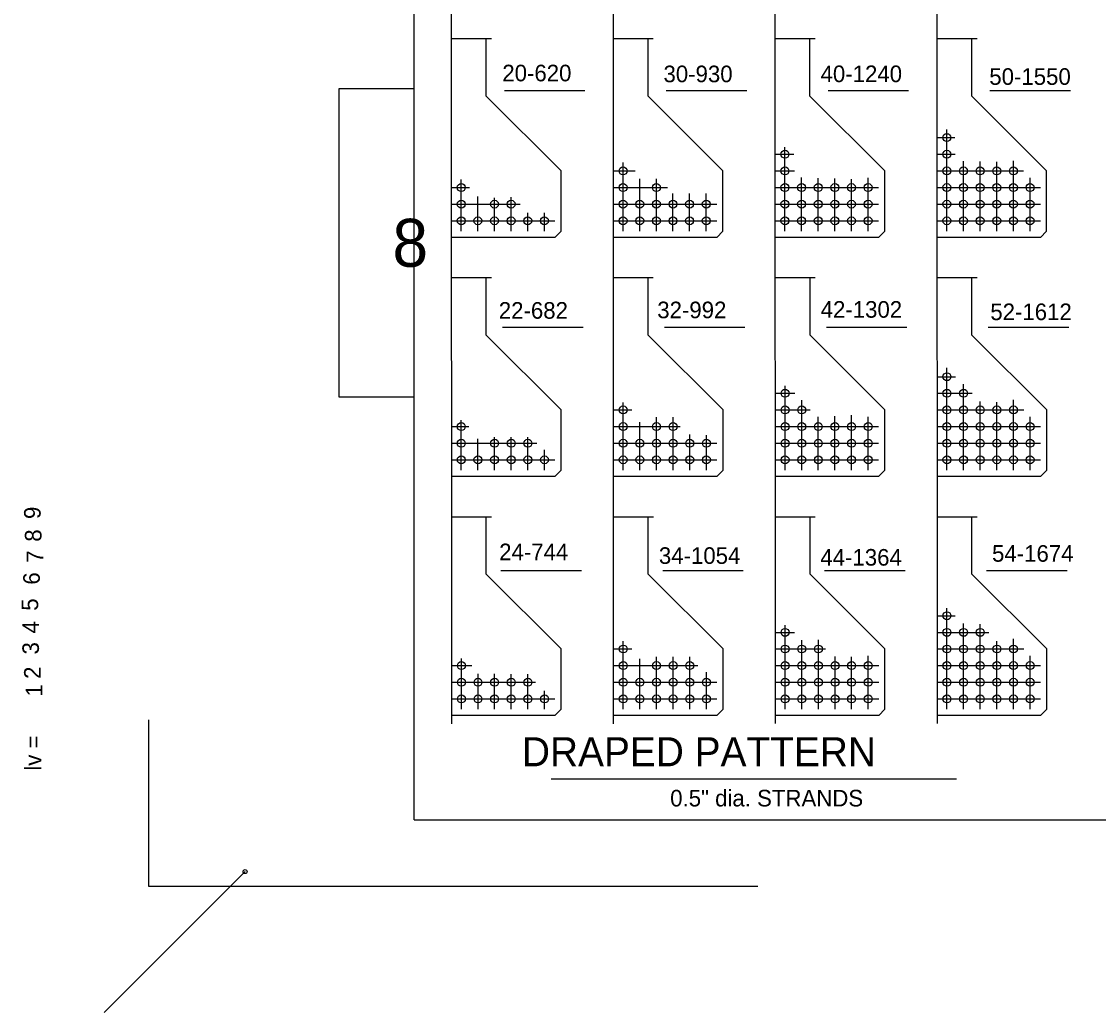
# Model space of a CAD drawing. Extents: x 1005 to 1123, y 2008 to 2074.
# Drawn here: x 1006.11 to 1027.73, y 2009.17 to 2029.07 of the extents above; entities that cross this region are included whole.
import ezdxf

# ---------------------------------------------------------------- set-up
doc = ezdxf.new("R2010")
doc.units = 0
for name, color, linetype in [('Level 1', 7, 'Continuous'), ('Level 2', 7, 'Continuous'), ('Level 3', 7, 'Continuous'), ('Level 4', 7, 'Continuous'), ('Level 49', 7, 'Continuous'), ('Level 5', 7, 'Continuous'), ('Level 6', 7, 'Continuous'), ('Level 7', 7, 'Continuous'), ('Level 8', 7, 'Continuous'), ('Level 9', 7, 'Continuous')]:
    doc.layers.add(name, color=color, linetype=linetype)

msp = doc.modelspace()

# ---------------------------------------------------------------- linework, layer by layer
at = {"layer": 'Level 1'}
for p, q in [((1013.989, 2013.041), (1013.989, 2069.04)), ((1008.656, 2015.048), (1008.656, 2011.708)), ((1013.989, 2013.041), (1097.657, 2013.041)), ((1008.656, 2011.708), (1020.89, 2011.708))]:
    msp.add_line(p, q, dxfattribs=at)
msp.add_lwpolyline([(1013.989, 2027.72), (1012.476, 2027.72), (1012.476, 2021.53), (1013.989, 2021.53)], close=True, dxfattribs=at)
at = {"layer": 'Level 2'}
for p, q in [((1016.744, 2013.865), (1024.877, 2013.865)), ((1007.769, 2009.17), (1010.598, 2011.999))]:
    msp.add_line(p, q, dxfattribs=at)
at = {"layer": 'Level 49'}
msp.add_circle((1010.597, 2011.999), 0.0405, dxfattribs=at)
at = {"layer": 'Level 8'}
for p, q in [((1014.732, 2038.643), (1014.739, 2014.968)), ((1017.982, 2038.644), (1017.989, 2014.969)), ((1021.232, 2038.645), (1021.239, 2014.97)), ((1024.482, 2038.646), (1024.489, 2014.971)), ((1014.734, 2028.726), (1015.542, 2028.726)), ((1014.769, 2028.726), (1015.542, 2028.726)), ((1015.437, 2027.572), (1015.437, 2028.726)), ((1017.984, 2028.726), (1018.792, 2028.726)), ((1018.019, 2028.726), (1018.792, 2028.726)), ((1018.687, 2027.572), (1018.687, 2028.726)), ((1021.234, 2028.726), (1022.042, 2028.726)), ((1021.269, 2028.726), (1022.042, 2028.726)), ((1021.937, 2027.572), (1021.937, 2028.726)), ((1024.484, 2028.726), (1025.292, 2028.726)), ((1024.519, 2028.726), (1025.292, 2028.726)), ((1025.187, 2027.572), (1025.187, 2028.726)), ((1016.94, 2026.069), (1015.437, 2027.572)), ((1015.802, 2027.681), (1017.418, 2027.681)), ((1020.19, 2026.069), (1018.687, 2027.572)), ((1019.052, 2027.681), (1020.668, 2027.681)), ((1023.44, 2026.069), (1021.937, 2027.572)), ((1022.302, 2027.681), (1023.918, 2027.681)), ((1026.69, 2026.069), (1025.187, 2027.572)), ((1025.552, 2027.681), (1027.168, 2027.681)), ((1024.686, 2024.858), (1024.686, 2026.898)), ((1024.485, 2026.737), (1024.846, 2026.737)), ((1021.436, 2024.858), (1021.436, 2026.549)), ((1018.186, 2024.858), (1018.186, 2026.237)), ((1021.235, 2026.403), (1021.616, 2026.403)), ((1024.485, 2026.403), (1024.856, 2026.403)), ((1025.02, 2024.858), (1025.02, 2026.268)), ((1025.354, 2024.858), (1025.354, 2026.258)), ((1025.688, 2024.858), (1025.688, 2026.248)), ((1026.022, 2024.858), (1026.022, 2026.271)), ((1016.94, 2024.858), (1016.94, 2026.069)), ((1017.986, 2026.069), (1018.429, 2026.069)), ((1020.19, 2024.858), (1020.19, 2026.069)), ((1021.235, 2026.069), (1021.626, 2026.069)), ((1023.44, 2024.858), (1023.44, 2026.069)), ((1024.485, 2026.069), (1026.228, 2026.069)), ((1026.69, 2024.858), (1026.69, 2026.069)), ((1014.936, 2024.858), (1014.936, 2025.898)), ((1018.52, 2024.858), (1018.52, 2025.909)), ((1018.854, 2024.858), (1018.854, 2025.909)), ((1021.77, 2024.858), (1021.77, 2025.938)), ((1022.104, 2024.858), (1022.104, 2025.926)), ((1022.438, 2024.858), (1022.438, 2025.915)), ((1022.772, 2024.858), (1022.772, 2025.903)), ((1023.106, 2024.858), (1023.106, 2025.933)), ((1026.356, 2024.858), (1026.356, 2025.933)), ((1014.735, 2025.735), (1015.1, 2025.735)), ((1017.985, 2025.735), (1019.079, 2025.735)), ((1019.188, 2024.858), (1019.188, 2025.617)), ((1019.522, 2024.858), (1019.522, 2025.617)), ((1019.856, 2024.858), (1019.856, 2025.617)), ((1021.235, 2025.735), (1023.315, 2025.735)), ((1024.485, 2025.735), (1026.565, 2025.735)), ((1014.736, 2025.401), (1016.122, 2025.401)), ((1015.27, 2024.858), (1015.27, 2025.557)), ((1015.604, 2024.858), (1015.604, 2025.529)), ((1015.938, 2024.858), (1015.938, 2025.541)), ((1017.985, 2025.401), (1020.065, 2025.401)), ((1021.235, 2025.401), (1023.315, 2025.401)), ((1024.485, 2025.401), (1026.565, 2025.401)), ((1016.272, 2024.858), (1016.272, 2025.23)), ((1016.606, 2024.858), (1016.606, 2025.23)), ((1014.736, 2025.067), (1016.815, 2025.067)), ((1017.986, 2025.067), (1020.065, 2025.067)), ((1021.236, 2025.067), (1023.315, 2025.067)), ((1024.486, 2025.067), (1026.565, 2025.067)), ((1016.815, 2024.733), (1014.736, 2024.733)), ((1016.815, 2024.733), (1016.94, 2024.858)), ((1020.065, 2024.733), (1017.986, 2024.733)), ((1020.065, 2024.733), (1020.19, 2024.858)), ((1023.315, 2024.733), (1021.236, 2024.733)), ((1023.315, 2024.733), (1023.44, 2024.858)), ((1026.565, 2024.733), (1024.486, 2024.733)), ((1026.565, 2024.733), (1026.69, 2024.858)), ((1014.735, 2023.926), (1015.543, 2023.926)), ((1014.771, 2023.926), (1015.543, 2023.926)), ((1015.439, 2022.772), (1015.439, 2023.926)), ((1017.985, 2023.926), (1018.793, 2023.926)), ((1018.021, 2023.926), (1018.793, 2023.926)), ((1018.689, 2022.772), (1018.689, 2023.926)), ((1021.235, 2023.926), (1022.043, 2023.926)), ((1021.271, 2023.926), (1022.043, 2023.926)), ((1021.939, 2022.772), (1021.939, 2023.926)), ((1024.485, 2023.926), (1025.293, 2023.926)), ((1024.521, 2023.926), (1025.293, 2023.926)), ((1025.189, 2022.772), (1025.189, 2023.926)), ((1016.942, 2021.269), (1015.439, 2022.772)), ((1015.768, 2022.932), (1017.383, 2022.932)), ((1020.192, 2021.269), (1018.689, 2022.772)), ((1019.018, 2022.932), (1020.633, 2022.932)), ((1023.442, 2021.269), (1021.939, 2022.772)), ((1022.268, 2022.932), (1023.883, 2022.932)), ((1026.692, 2021.269), (1025.189, 2022.772)), ((1025.518, 2022.932), (1027.133, 2022.932)), ((1024.688, 2020.058), (1024.688, 2022.116)), ((1024.486, 2021.937), (1024.863, 2021.937)), ((1021.438, 2020.058), (1021.438, 2021.755)), ((1025.022, 2020.058), (1025.022, 2021.787)), ((1021.236, 2021.603), (1021.631, 2021.603)), ((1021.772, 2020.058), (1021.772, 2021.463)), ((1024.486, 2021.603), (1025.193, 2021.603)), ((1026.024, 2020.058), (1026.024, 2021.471)), ((1016.942, 2020.058), (1016.942, 2021.269)), ((1017.987, 2021.269), (1018.362, 2021.269)), ((1018.188, 2020.058), (1018.188, 2021.416)), ((1020.192, 2020.058), (1020.192, 2021.269)), ((1021.237, 2021.269), (1021.939, 2021.269)), ((1023.442, 2020.058), (1023.442, 2021.269)), ((1024.487, 2021.269), (1026.229, 2021.269)), ((1025.356, 2020.058), (1025.356, 2021.436)), ((1025.69, 2020.058), (1025.69, 2021.426)), ((1026.692, 2020.058), (1026.692, 2021.269)), ((1014.938, 2020.058), (1014.938, 2021.066)), ((1018.522, 2020.058), (1018.522, 2021.021)), ((1018.856, 2020.058), (1018.856, 2021.121)), ((1019.19, 2020.058), (1019.19, 2021.121)), ((1022.106, 2020.058), (1022.106, 2021.129)), ((1022.44, 2020.058), (1022.44, 2021.147)), ((1022.774, 2020.058), (1022.774, 2021.164)), ((1023.108, 2020.058), (1023.108, 2021.133)), ((1026.358, 2020.058), (1026.358, 2021.133)), ((1014.737, 2020.935), (1015.09, 2020.935)), ((1017.987, 2020.935), (1019.333, 2020.935)), ((1021.237, 2020.935), (1023.317, 2020.935)), ((1024.487, 2020.935), (1026.567, 2020.935)), ((1014.737, 2020.601), (1016.456, 2020.601)), ((1015.272, 2020.058), (1015.272, 2020.687)), ((1015.606, 2020.058), (1015.606, 2020.723)), ((1015.94, 2020.058), (1015.94, 2020.723)), ((1016.274, 2020.058), (1016.274, 2020.723)), ((1017.987, 2020.601), (1020.067, 2020.601)), ((1019.524, 2020.058), (1019.524, 2020.775)), ((1019.858, 2020.058), (1019.858, 2020.766)), ((1021.237, 2020.601), (1023.317, 2020.601)), ((1024.487, 2020.601), (1026.567, 2020.601)), ((1016.608, 2020.058), (1016.608, 2020.468)), ((1014.737, 2020.267), (1016.817, 2020.267)), ((1017.987, 2020.267), (1020.067, 2020.267)), ((1021.237, 2020.267), (1023.317, 2020.267)), ((1024.487, 2020.267), (1026.567, 2020.267)), ((1016.817, 2019.933), (1016.942, 2020.058)), ((1020.067, 2019.933), (1020.192, 2020.058)), ((1023.317, 2019.933), (1023.442, 2020.058)), ((1026.567, 2019.933), (1026.692, 2020.058)), ((1016.817, 2019.933), (1014.737, 2019.933)), ((1020.067, 2019.933), (1017.987, 2019.933)), ((1023.317, 2019.933), (1021.237, 2019.933)), ((1026.567, 2019.933), (1024.487, 2019.933)), ((1014.737, 2019.126), (1015.545, 2019.126)), ((1014.772, 2019.126), (1015.545, 2019.126)), ((1015.44, 2017.972), (1015.44, 2019.126)), ((1017.987, 2019.126), (1018.795, 2019.126)), ((1018.022, 2019.126), (1018.795, 2019.126)), ((1018.69, 2017.972), (1018.69, 2019.126)), ((1021.237, 2019.126), (1022.045, 2019.126)), ((1021.272, 2019.126), (1022.045, 2019.126)), ((1021.94, 2017.972), (1021.94, 2019.126)), ((1024.487, 2019.126), (1025.295, 2019.126)), ((1024.522, 2019.126), (1025.295, 2019.126)), ((1025.19, 2017.972), (1025.19, 2019.126)), ((1015.733, 2018.046), (1017.349, 2018.046)), ((1018.983, 2018.046), (1020.599, 2018.046)), ((1022.233, 2018.046), (1023.849, 2018.046)), ((1025.483, 2018.046), (1027.099, 2018.046)), ((1016.943, 2016.469), (1015.44, 2017.972)), ((1020.193, 2016.469), (1018.69, 2017.972)), ((1023.443, 2016.469), (1021.94, 2017.972)), ((1026.693, 2016.469), (1025.19, 2017.972)), ((1024.488, 2017.137), (1024.851, 2017.137)), ((1024.689, 2015.258), (1024.689, 2017.289)), ((1021.439, 2015.258), (1021.439, 2016.949)), ((1025.023, 2015.258), (1025.023, 2016.984)), ((1025.357, 2015.258), (1025.357, 2016.97)), ((1021.238, 2016.803), (1021.626, 2016.803)), ((1024.488, 2016.803), (1025.53, 2016.803)), ((1018.189, 2015.258), (1018.189, 2016.623)), ((1021.773, 2015.258), (1021.773, 2016.644)), ((1022.107, 2015.258), (1022.107, 2016.65)), ((1025.691, 2015.258), (1025.691, 2016.625)), ((1026.025, 2015.258), (1026.025, 2016.671)), ((1014.939, 2015.258), (1014.939, 2016.276)), ((1016.943, 2015.258), (1016.943, 2016.469)), ((1017.988, 2016.469), (1018.36, 2016.469)), ((1018.523, 2015.258), (1018.523, 2016.272)), ((1018.857, 2015.258), (1018.857, 2016.309)), ((1019.191, 2015.258), (1019.191, 2016.309)), ((1019.525, 2015.258), (1019.525, 2016.309)), ((1020.193, 2015.258), (1020.193, 2016.469)), ((1021.238, 2016.469), (1022.248, 2016.469)), ((1022.441, 2015.258), (1022.441, 2016.316)), ((1022.775, 2015.258), (1022.775, 2016.312)), ((1023.109, 2015.258), (1023.109, 2016.333)), ((1023.443, 2015.258), (1023.443, 2016.469)), ((1024.488, 2016.469), (1026.231, 2016.469)), ((1026.359, 2015.258), (1026.359, 2016.333)), ((1026.693, 2015.258), (1026.693, 2016.469)), ((1014.738, 2016.135), (1015.148, 2016.135)), ((1017.988, 2016.135), (1019.689, 2016.135)), ((1021.238, 2016.135), (1023.318, 2016.135)), ((1024.488, 2016.135), (1026.568, 2016.135)), ((1015.273, 2015.258), (1015.273, 2015.971)), ((1015.607, 2015.258), (1015.607, 2015.968)), ((1015.941, 2015.258), (1015.941, 2015.965)), ((1016.275, 2015.258), (1016.275, 2015.961)), ((1019.859, 2015.258), (1019.859, 2016.005)), ((1014.738, 2015.801), (1016.428, 2015.801)), ((1016.609, 2015.258), (1016.609, 2015.629)), ((1017.988, 2015.801), (1020.068, 2015.801)), ((1021.238, 2015.801), (1023.318, 2015.801)), ((1024.488, 2015.801), (1026.568, 2015.801)), ((1014.738, 2015.467), (1016.818, 2015.467)), ((1017.988, 2015.467), (1020.068, 2015.467)), ((1021.238, 2015.467), (1023.318, 2015.467)), ((1024.488, 2015.467), (1026.568, 2015.467)), ((1016.818, 2015.133), (1016.943, 2015.258)), ((1020.068, 2015.133), (1020.193, 2015.258)), ((1023.318, 2015.133), (1023.443, 2015.258)), ((1026.568, 2015.133), (1026.693, 2015.258)), ((1016.818, 2015.133), (1014.739, 2015.133)), ((1020.068, 2015.133), (1017.989, 2015.133)), ((1023.318, 2015.133), (1021.239, 2015.133)), ((1026.568, 2015.133), (1024.489, 2015.133))]:
    msp.add_line(p, q, dxfattribs=at)
for centre in [(1024.686, 2026.737), (1021.436, 2026.403), (1024.686, 2026.403), (1018.186, 2026.069), (1021.436, 2026.069), (1024.686, 2026.069), (1025.02, 2026.069), (1025.354, 2026.069), (1025.688, 2026.069), (1026.022, 2026.069), (1014.936, 2025.735), (1018.186, 2025.735), (1018.854, 2025.735), (1021.436, 2025.735), (1021.77, 2025.735), (1022.104, 2025.735), (1022.438, 2025.735), (1022.772, 2025.735), (1023.106, 2025.735), (1024.686, 2025.735), (1025.02, 2025.735), (1025.354, 2025.735), (1025.688, 2025.735), (1026.022, 2025.735), (1026.356, 2025.735), (1014.936, 2025.401), (1015.604, 2025.401), (1015.938, 2025.401), (1018.186, 2025.401), (1018.52, 2025.401), (1018.854, 2025.401), (1019.188, 2025.401), (1019.522, 2025.401), (1019.856, 2025.401), (1021.436, 2025.401), (1021.77, 2025.401), (1022.104, 2025.401), (1022.438, 2025.401), (1022.772, 2025.401), (1023.106, 2025.401), (1024.686, 2025.401), (1025.02, 2025.401), (1025.354, 2025.401), (1025.688, 2025.401), (1026.022, 2025.401), (1026.356, 2025.401), (1014.936, 2025.067), (1015.27, 2025.067), (1015.604, 2025.067), (1015.938, 2025.067), (1016.272, 2025.067), (1016.606, 2025.067), (1018.186, 2025.067), (1018.52, 2025.067), (1018.854, 2025.067), (1019.188, 2025.067), (1019.522, 2025.067), (1019.856, 2025.067), (1021.436, 2025.067), (1021.77, 2025.067), (1022.104, 2025.067), (1022.438, 2025.067), (1022.772, 2025.067), (1023.106, 2025.067), (1024.686, 2025.067), (1025.02, 2025.067), (1025.354, 2025.067), (1025.688, 2025.067), (1026.022, 2025.067), (1026.356, 2025.067), (1024.688, 2021.937), (1021.438, 2021.603), (1024.688, 2021.603), (1025.022, 2021.603), (1018.188, 2021.269), (1021.438, 2021.269), (1021.772, 2021.269), (1024.688, 2021.269), (1025.022, 2021.269), (1025.356, 2021.269), (1025.69, 2021.269), (1026.024, 2021.269), (1014.938, 2020.935), (1018.188, 2020.935), (1018.856, 2020.935), (1019.19, 2020.935), (1021.438, 2020.935), (1021.772, 2020.935), (1022.106, 2020.935), (1022.44, 2020.935), (1022.774, 2020.935), (1023.108, 2020.935), (1024.688, 2020.935), (1025.022, 2020.935), (1025.356, 2020.935), (1025.69, 2020.935), (1026.024, 2020.935), (1026.358, 2020.935), (1014.938, 2020.601), (1015.606, 2020.601), (1015.94, 2020.601), (1016.274, 2020.601), (1018.188, 2020.601), (1018.522, 2020.601), (1018.856, 2020.601), (1019.19, 2020.601), (1019.524, 2020.601), (1019.858, 2020.601), (1021.438, 2020.601), (1021.772, 2020.601), (1022.106, 2020.601), (1022.44, 2020.601), (1022.774, 2020.601), (1023.108, 2020.601), (1024.688, 2020.601), (1025.022, 2020.601), (1025.356, 2020.601), (1025.69, 2020.601), (1026.024, 2020.601), (1026.358, 2020.601), (1014.938, 2020.267), (1015.272, 2020.267), (1015.606, 2020.267), (1015.94, 2020.267), (1016.274, 2020.267), (1016.608, 2020.267), (1018.188, 2020.267), (1018.522, 2020.267), (1018.856, 2020.267), (1019.19, 2020.267), (1019.524, 2020.267), (1019.858, 2020.267), (1021.438, 2020.267), (1021.772, 2020.267), (1022.106, 2020.267), (1022.44, 2020.267), (1022.774, 2020.267), (1023.108, 2020.267), (1024.688, 2020.267), (1025.022, 2020.267), (1025.356, 2020.267), (1025.69, 2020.267), (1026.024, 2020.267), (1026.358, 2020.267), (1024.689, 2017.137), (1021.439, 2016.803), (1024.689, 2016.803), (1025.023, 2016.803), (1025.357, 2016.803), (1018.189, 2016.469), (1021.439, 2016.469), (1021.773, 2016.469), (1022.107, 2016.469), (1024.689, 2016.469), (1025.023, 2016.469), (1025.357, 2016.469), (1025.691, 2016.469), (1026.025, 2016.469), (1014.939, 2016.135), (1018.189, 2016.135), (1018.857, 2016.135), (1019.191, 2016.135), (1019.525, 2016.135), (1021.439, 2016.135), (1021.773, 2016.135), (1022.107, 2016.135), (1022.441, 2016.135), (1022.775, 2016.135), (1023.109, 2016.135), (1024.689, 2016.135), (1025.023, 2016.135), (1025.357, 2016.135), (1025.691, 2016.135), (1026.025, 2016.135), (1026.359, 2016.135), (1014.939, 2015.801), (1015.273, 2015.801), (1015.607, 2015.801), (1015.941, 2015.801), (1016.275, 2015.801), (1018.189, 2015.801), (1018.523, 2015.801), (1018.857, 2015.801), (1019.191, 2015.801), (1019.525, 2015.801), (1019.859, 2015.801), (1021.439, 2015.801), (1021.773, 2015.801), (1022.107, 2015.801), (1022.441, 2015.801), (1022.775, 2015.801), (1023.109, 2015.801), (1024.689, 2015.801), (1025.023, 2015.801), (1025.357, 2015.801), (1025.691, 2015.801), (1026.025, 2015.801), (1026.359, 2015.801), (1014.939, 2015.467), (1015.273, 2015.467), (1015.607, 2015.467), (1015.941, 2015.467), (1016.275, 2015.467), (1016.609, 2015.467), (1018.189, 2015.467), (1018.523, 2015.467), (1018.857, 2015.467), (1019.191, 2015.467), (1019.525, 2015.467), (1019.859, 2015.467), (1021.439, 2015.467), (1021.773, 2015.467), (1022.107, 2015.467), (1022.441, 2015.467), (1022.775, 2015.467), (1023.109, 2015.467), (1024.689, 2015.467), (1025.023, 2015.467), (1025.357, 2015.467), (1025.691, 2015.467), (1026.025, 2015.467), (1026.359, 2015.467)]:
    msp.add_circle(centre, 0.0797, dxfattribs=at)

# ---------------------------------------------------------------- texts
at = {"layer": 'Level 1'}
msp.add_text('8', height=0.963, dxfattribs=at).set_placement((1013.555, 2024.144))
msp.add_text('1', height=0.333, rotation=90, dxfattribs=at).set_placement((1006.526, 2015.514))
at = {"layer": 'Level 2'}
for s, height, p in [('2', 0.333, (1006.492, 2015.869)), ('lv =', 0.3333, (1006.509, 2014.026))]:
    msp.add_text(s, height=height, rotation=90, dxfattribs=at).set_placement(p)
msp.add_text('  DRAPED PATTERN', height=0.58333, dxfattribs=at).set_placement((1015.722, 2014.114))
at = {"layer": 'Level 3'}
msp.add_text('3', height=0.333, rotation=90, dxfattribs=at).set_placement((1006.458, 2016.359))
at = {"layer": 'Level 4'}
msp.add_text('4', height=0.333, rotation=90, dxfattribs=at).set_placement((1006.458, 2016.781))
at = {"layer": 'Level 5'}
msp.add_text('5', height=0.333, rotation=90, dxfattribs=at).set_placement((1006.442, 2017.237))
at = {"layer": 'Level 6'}
msp.add_text('6', height=0.333, rotation=90, dxfattribs=at).set_placement((1006.475, 2017.761))
at = {"layer": 'Level 7'}
msp.add_text('7', height=0.333, rotation=90, dxfattribs=at).set_placement((1006.543, 2018.201))
at = {"layer": 'Level 8'}
for s, height, p in [('20-620 ', 0.3333, (1015.761, 2027.868)), ('30-930 ', 0.3333, (1018.997, 2027.85)), ('40-1240', 0.3333, (1022.151, 2027.852)), ('50-1550', 0.3333, (1025.539, 2027.797)), ('22-682 ', 0.3333, (1015.691, 2023.101)), ('32-992 ', 0.3333, (1018.872, 2023.111)), ('42-1302', 0.3333, (1022.153, 2023.121)), ('52-1612', 0.3333, (1025.559, 2023.073)), ('24-744 ', 0.3333, (1015.698, 2018.252)), ('34-1054 ', 0.3333, (1018.905, 2018.178)), ('44-1364', 0.3333, (1022.147, 2018.143)), ('54-1674', 0.3333, (1025.594, 2018.221)), ('0.5" dia. STRANDS', 0.33333, (1019.132, 2013.307))]:
    msp.add_text(s, height=height, dxfattribs=at).set_placement(p)
msp.add_text('8', height=0.333, rotation=90, dxfattribs=at).set_placement((1006.509, 2018.623))
at = {"layer": 'Level 9'}
msp.add_text('9', height=0.333, rotation=90, dxfattribs=at).set_placement((1006.492, 2019.079))

doc.saveas('drawing.dxf')
